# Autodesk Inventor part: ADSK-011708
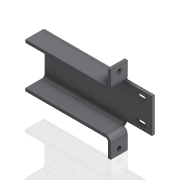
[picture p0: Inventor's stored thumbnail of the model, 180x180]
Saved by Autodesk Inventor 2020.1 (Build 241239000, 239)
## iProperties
Created: 2000-03
Part Number: ADSK-011708
Material: 1.0312 DC05
Document SubType Name: Tôlerie
Designer: cmcgourin
Density: 1 g/cm^3
Sheet Metal Rule: Stahlblech 1.0312 - DC05 -   6.0 mm
Appearance: Metal-Steel(Polish)
Mass: 246.165 g
Surface Area: 898.034 cm^2
Volume: 246.165 cm^3
Flat Pattern Width: 24.5 cm
Flat Pattern Length: 18.1143 cm
Flat Pattern Area: 443.801 cm^2
Sheet Metal Width: 245,000 mm
Sheet Metal Length: 181,143 mm
Sheet Metal Area: 44380,123 mm^2
Control State: 0
Master: False
Checked Out: False
Shininess: 25.0
Length Units: 11269
Angle Units: 11279
Time Units: 11290
Mass Units: 11283
Length Display Precision: 3
Angle Display Precision: 2
Compacted: True
Cutlength: 23.25
Material Desc: Material Description goes here
Material_Number: Pearson
G_L: 245x181,1 mm
Thickness: 6,000 mm
Dimensions: 178x50x245 mm
Mass: 0,246 kg
Semi finished: Stahlblech 1.0312 - DC05 -   6.0 mm
VLT_Material: 1.0312 DC05
DocNumber: ADSK-011708.ipt
Folder: 01 - Themengebiete\Simplification\01 - Packaging machine\
VDS_Category: 3D Komponenten
Density: 0.0
Volumn: 0.0
Area: 0.0
PropertySet Name: Model Information
Author: cmcgourin
Revision Number: -
Title: holding plate
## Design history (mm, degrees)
node "Solide1"
  node "Face1"
  node "Flange1"
  node "Flange3"
  node "Cut1" dims "d19" = 6 (= Thickness), "d20" = 0
  node "Flange4"
  node "Flange5"
  node "Hole1" dims "d28" = 9, "d29" = 9.525, "d30" = 6.35, "d31" = 60 deg, "d32" = 19.05, "d33" = 118 deg, "d77" = 6
  node "Hole2" dims "d35" = 9, "d36" = 9.525, "d37" = 6.35, "d38" = 60 deg, "d39" = 19.05, "d40" = 118 deg, "d76" = 6
  node "Cut2" dims "d51" = 6 (= Thickness), "d52" = 0
  node "Hole3" dims "d53" = 6.6, "d54" = 9.525, "d55" = 6.35, "d56" = 60 deg, "d57" = 19.05, "d58" = 118 deg, "d83" = 6
sketch "Sketch2"
  geometry: L1 (-122.5, 51)-(122.5, 51); L2 (122.5, 51)-(122.5, -51); L3 (122.5, -51)-(-122.5, -51); L4 (-122.5, -51)-(-122.5, 51); 3 further points
  constraints: 8 end point, 2 midpoint, 2 parallel, 1 horizontal, 1 horizontal alignment, 1 perpendicular, 1 vertical alignment
  dimensions: "d6" = 102 distance of L3.end L1.start; "d7" = 245 distance of L2.end L3.end
sketch "Sketch12"
  geometry: L1 (-65.5, 60.5)-(-22.5, 60.5); L2 (-22.5, 60.5)-(-22.5, 17.5); L3 (-22.5, 17.5)-(-65.5, 17.5); L4 (-65.5, 17.5)-(-65.5, 60.5); L5 (0, 78)-(0, 0) reference; 6 further points
  constraints: 8 end point, 4 coincident, 2 midpoint, 2 parallel, 1 horizontal, 1 horizontal alignment, 1 perpendicular
  dimensions: "d80" = 22.5 distance between parallel lines of L5 L2; "d81" = 43 distance of L1.start L1.end; "d82" = 43 distance of L3.end L1.start (= d81)
sketch "Sketch9"
  geometry: L1 (0, 0)-(38, 0) reference; L2 (38, 0)-(0, 0) reference; 2 further points
  constraints: 1 midpoint, 1 vertical alignment
  dimensions: "d27" = 12.5 distance from line of L1 point (19, -12.5)
sketch "Sketch10"
  geometry: L1 (38, 0)-(0, 0) reference; L2 (0, 0)-(38, 0) reference; 2 further points
  constraints: 1 midpoint, 1 vertical alignment
  dimensions: "d34" = 12.5 distance from line of L1 point (19, 12.5)
sketch "Sketch11"
  geometry: L1 (-245, 0)-(-245, 78) reference; L2 (-226.25, 69.5)-(-213.75, 69.5); L3 (-213.75, 59.5)-(-226.25, 59.5); L4 (-226.25, 18.5)-(-213.75, 18.5); L5 (-213.75, 8.5)-(-226.25, 8.5); L6 (-226.25, 64.5)-(-213.75, 64.5); L7 (-226.25, 13.5)-(-213.75, 13.5); L8 (-220, 13.5)-(-220, 64.5); A1 r 5 centre (-226.25, 64.5) between (-226.25, 69.5) and (-226.25, 59.5); A2 r 5 centre (-213.75, 64.5) between (-213.75, 59.5) and (-213.75, 69.5); A3 r 5 centre (-226.25, 13.5) between (-226.25, 18.5) and (-226.25, 8.5); A4 r 5 centre (-213.75, 13.5) between (-213.75, 8.5) and (-213.75, 18.5); 2 further points
  constraints: 14 end point, 8 point on circle, 8 tangent, 4 centre point, 4 horizontal, 4 midpoint, 2 equal radius, 2 parallel, 1 horizontal alignment
  dimensions: "d43" = 10 distance between parallel lines of L4 L5 (= d44); "d44" = 10 distance between parallel lines of L2 L3; "d45" = 12.5 distance of L3.start L3.end; "d46" = 12.5 distance of L4.start L4.end (= d45); "d78" = 51 distance of L8.start L8.end; "d79" = 25 distance between parallel lines of L1 L8
node "Plate1" dims "d71" = 6 (= Thickness)
node "Plate2" dims "d9" = 44, "d10" = 90 deg, "d11" = 6 (= BendRadius), "d59" = 6 (= BendReliefWidth), "d60" = 3 (= BendReliefDepth), "d61" = 12 (= MinimumRemnant), "d71" = 6 (= Thickness), "d72" = 6 (= TransitionRadius), "SeamGap" = 0.00508
node "Bend1" dims "d9" = 44, "d10" = 90 deg, "d11" = 6 (= BendRadius), "d59" = 6 (= BendReliefWidth), "d60" = 3 (= BendReliefDepth), "d61" = 12 (= MinimumRemnant), "d71" = 6 (= Thickness), "d72" = 6 (= TransitionRadius), "SeamGap" = 0.00508
node "Plate4" dims "d15" = 44, "d16" = 90 deg, "d17" = 6 (= BendRadius), "d62" = 6 (= BendReliefWidth), "d63" = 3 (= BendReliefDepth), "d64" = 12 (= MinimumRemnant), "d71" = 6 (= Thickness), "d73" = 6 (= TransitionRadius), "SeamGap" = 0.00508
node "Bend3" dims "d15" = 44, "d16" = 90 deg, "d17" = 6 (= BendRadius), "d62" = 6 (= BendReliefWidth), "d63" = 3 (= BendReliefDepth), "d64" = 12 (= MinimumRemnant), "d71" = 6 (= Thickness), "d73" = 6 (= TransitionRadius), "SeamGap" = 0.00508
sketch "Sketch6"
  geometry: L1 (245, 38)-(0, 38) reference; L2 (245, 38)-(245, 0) reference; L3 (245, 0)-(195, 0); L4 (195, 0)-(195, 38); L5 (195, 38)-(245, 38); L6 (245, 38)-(245, 0)
  constraints: 8 end point, 2 parallel, 1 horizontal, 1 perpendicular, 1 point on line
  dimensions: "d18" = 50 distance of L2.end L3.end
sketch "Sketch7"
  geometry: L1 (0, 38)-(-38, 38); L2 (-38, 38)-(-38, 0); 1 other entity
  constraints: 4 end point, 4 other
node "Plate5" dims "d21" = 38, "d22" = 90 deg, "d23" = 6 (= BendRadius), "d65" = 6 (= BendReliefWidth), "d66" = 3 (= BendReliefDepth), "d67" = 12 (= MinimumRemnant), "d71" = 6 (= Thickness), "d74" = 6 (= TransitionRadius), "SeamGap" = 0.00508
node "Bend4" dims "d21" = 38, "d22" = 90 deg, "d23" = 6 (= BendRadius), "d65" = 6 (= BendReliefWidth), "d66" = 3 (= BendReliefDepth), "d67" = 12 (= MinimumRemnant), "d71" = 6 (= Thickness), "d74" = 6 (= TransitionRadius), "SeamGap" = 0.00508
sketch "Sketch8"
  geometry: L1 (0, -38)-(38, -38); L2 (38, -38)-(38, 0); 1 other entity
  constraints: 4 end point, 4 other
node "Plate6" dims "d24" = 38, "d25" = 90 deg, "d26" = 6 (= BendRadius), "d68" = 6 (= BendReliefWidth), "d69" = 3 (= BendReliefDepth), "d70" = 12 (= MinimumRemnant), "d71" = 6 (= Thickness), "d75" = 6 (= TransitionRadius), "SeamGap" = 0.00508
node "Bend5" dims "d24" = 38, "d25" = 90 deg, "d26" = 6 (= BendRadius), "d68" = 6 (= BendReliefWidth), "d69" = 3 (= BendReliefDepth), "d70" = 12 (= MinimumRemnant), "d71" = 6 (= Thickness), "d75" = 6 (= TransitionRadius), "SeamGap" = 0.00508
node "Corps solides"
node "Corps surfaciques"
sketch "Sketch3"
  geometry: L1 (245, 0)-(245, 44); L2 (245, 44)-(0, 44); 1 other entity
  constraints: 4 end point, 4 other
sketch "Sketch5"
  geometry: L1 (245, 0)-(245, 44); L2 (245, 44)-(0, 44); 1 other entity
  constraints: 4 end point, 4 other
feature "Definition1"
other parameters: "Thickness" = 6 (derived), "BendRadius" = 6 (= Thickness), "BendReliefWidth" = 6 (= Thickness), "BendReliefDepth" = 3 (= 0.5 x Thickness), "CornerReliefSize" = 24 (= 4 x Thickness), "MinimumRemnant" = 12 (= 2 x Thickness), "d8" = 6 (= BendRadius), "TransitionRadius" = 6 (= BendRadius), "TailleRayonJacobi" = 6 (= BendRadius), "TailleJeu" = 6 (= Thickness), "BendRadius" = 6, "BendReliefDepth" = 3, "BendReliefWidth" = 6, "CornerReliefSize" = 24, "MinimumRemnant" = 12, "TailleJeu" = 6, "TailleRayonJacobi" = 6, "Thickness" = 6, "TransitionRadius" = 6
